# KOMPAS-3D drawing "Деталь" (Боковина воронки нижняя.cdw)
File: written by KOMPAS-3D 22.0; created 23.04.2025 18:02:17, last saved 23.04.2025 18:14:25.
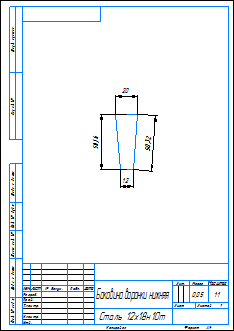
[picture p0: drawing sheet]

Sheet 1: A4, portrait

Document properties: Автор: Admin; Масса: 0.050341; Полное имя файла: Боковина низ 4шт.m3d

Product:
- Part/product: Деталь
    Масса: 0.009457

Title block, sheet 1: Наименование: Боковина воронки нижняя; Материал: Сталь 12х18н10т; Масса: 0,05; Количество листов документа: 1; Форматы листов документа: A4; stored path: D:\28.11.2016\3D модели\Абилимпикс\2025\Воронка квадратная\Боковина воронки верхняя.cdw

Views: Вид 1, Спереди
Referenced files in D:\28.11.2016\3D модели\Абилимпикс\2025\Воронка квадратная\: Боковина низ 4шт.m3d
Dimensions and other numbers on the sheet: 20; 12; 50,16; 50,32; 1:1; 1; 0,05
